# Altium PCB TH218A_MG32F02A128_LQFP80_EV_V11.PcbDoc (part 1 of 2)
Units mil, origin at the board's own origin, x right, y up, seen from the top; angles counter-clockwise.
Board outline 4370.08 x 2637.8 mil, 2 copper layers (Top Layer, Bottom Layer); 115 components, 136 nets, 568 pads, 236 vias.
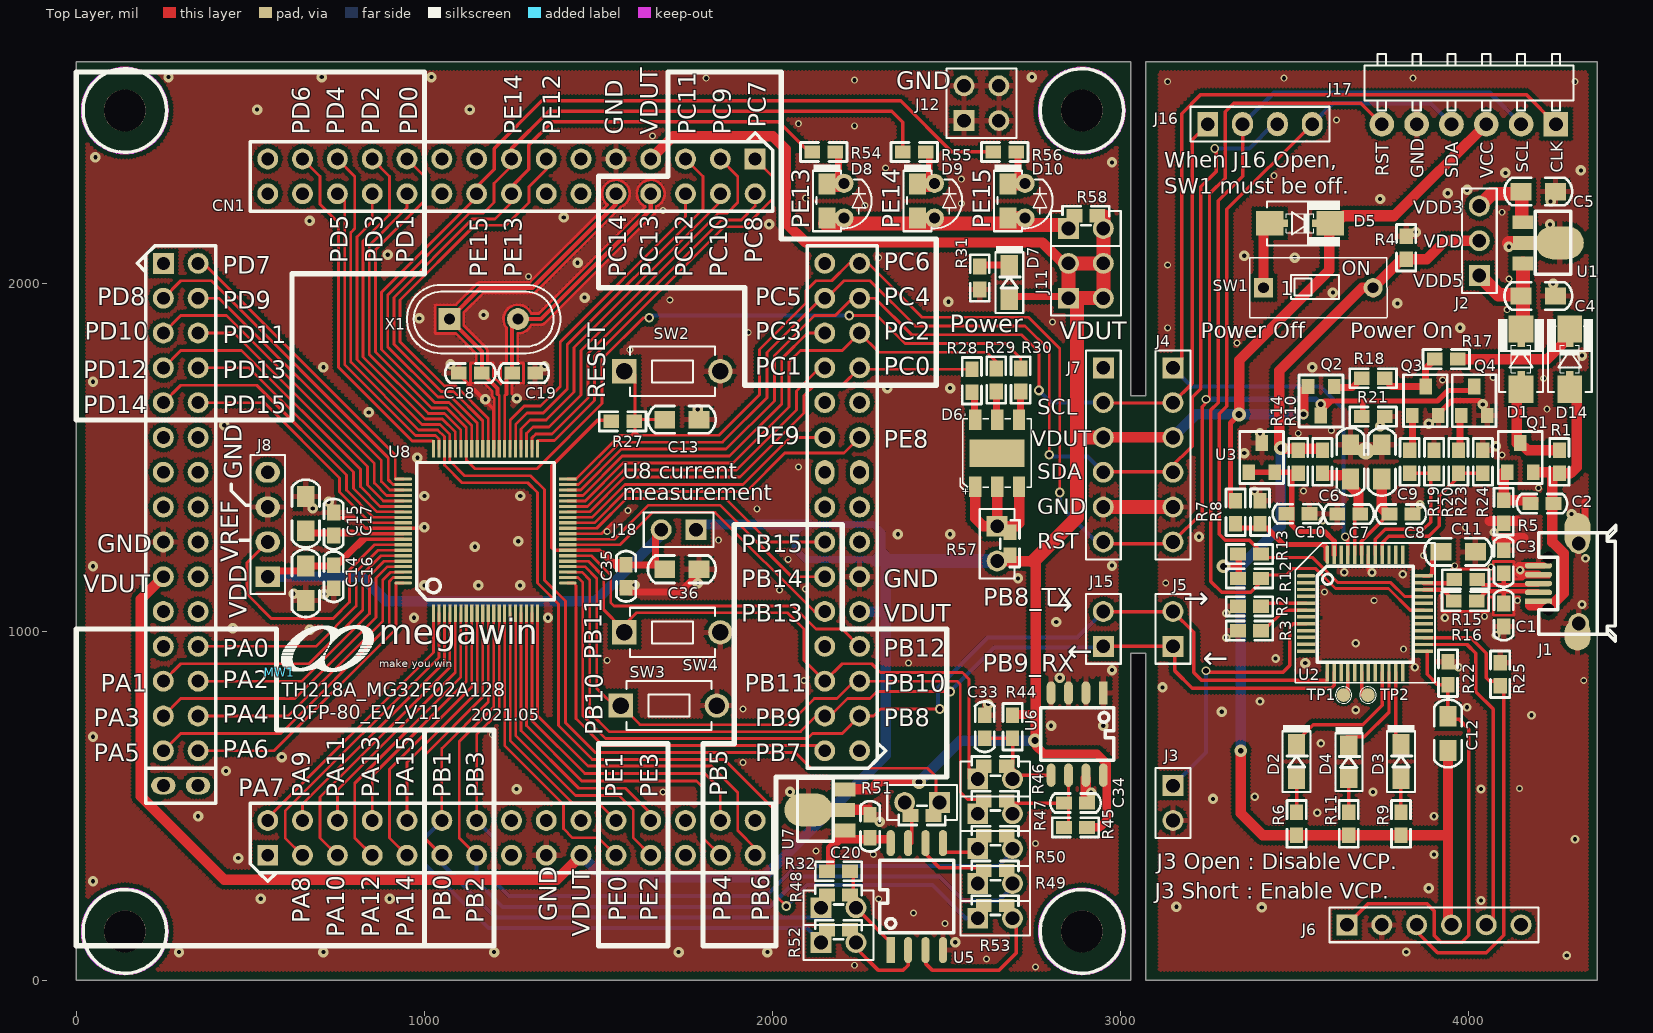
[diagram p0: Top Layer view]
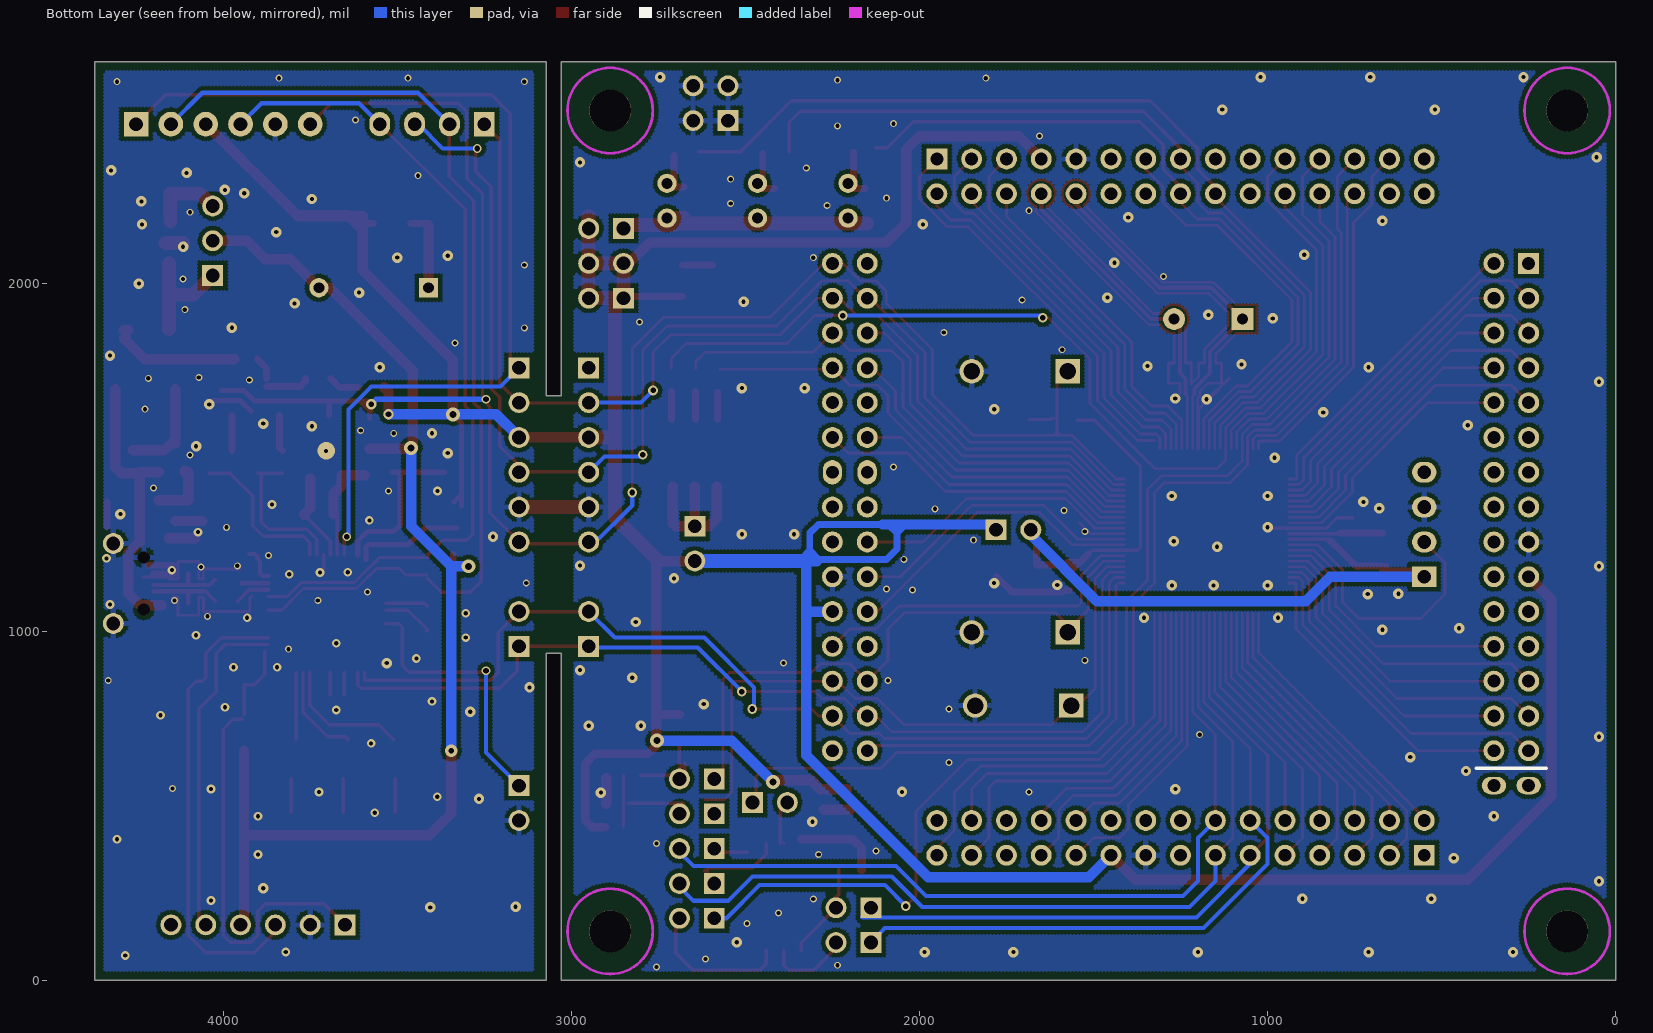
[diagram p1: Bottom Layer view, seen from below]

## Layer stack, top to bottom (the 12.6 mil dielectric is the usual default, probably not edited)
Top Layer: signal copper 1.4
Dielectric: dielectric 12.6, FR-4, Dk 4.8
Bottom Layer: signal copper 1.4

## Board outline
0,0 0,2637.8 3028.98,2637.8 3028.98,1678.74 3072.28,1678.74 3072.28,2637.8 4370.08,2637.8 4370.08,0 3072.28,0 3072.28,938.74 3028.98,938.74 3028.98,0

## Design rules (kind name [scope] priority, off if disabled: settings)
Clearance 12 [All] p1 off: gap=12
Clearance 7 [All] p2 off: gap=7
Clearance 6 [All] p3: gap=6
HoleSize 500-HoleSize [All] p1: absolutevalues=TRUE maxlimit=1500 minlimit=1 maxpercent=80.000 minpercent=20.000
PolygonConnect VIA [ISVIA] p1: connectstyle=Direct reliefconductorwidth=10 reliefentries=4 polygonreliefangle="90 Angle"
PolygonConnect "15 PolygonConnect" [All] p2: connectstyle=Relief reliefconductorwidth=15 reliefentries=4 polygonreliefangle="90 Angle"
RoomDefinition 2_MG32F02A128_V11 [InComponentClass('2_MG32F02A128_V11')] p1: confinementstyle=ConfineIn formatcopy=TRUE lockcomponents=FALSE outline -55,-85 4500,-85 4500,2740 -55,2740
RoomDefinition 1_MLink_V11 [InComponentClass('1_MLink_V11')] p2 off: confinementstyle=ConfineIn formatcopy=TRUE lockcomponents=FALSE outline -20,-126.26 4460,-126.26 4460,2920 -20,2920
RoutingVias [All] p1: holewidth=16 width=28 viastyle="Through Hole" minholewidth=16 minwidth=25 maxholewidth=28 maxwidth=50
ShortCircuit [All] p1 off: allowed=FALSE
SilkscreenOverComponentPads [All] p1: minsilkscreentomaskgap=10
SolderMaskExpansion [All] p1: expansion=4
UnRoutedNet [All] p1 off:
Width [All] p1: maxlimit=100 minlimit=6 preferedwidth=10
24 further rules are at their usual default settings.

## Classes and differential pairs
component class 1_MLink_V11: C1 C2 C3 C4 C5 C6 C7 C8 C9 C10 C11 C12 D1 D2 D3 D4 D5 D14 J1 J2 J3 J4 J5 J6 J16 J17 MW1 Q1 Q2 Q3 Q4 R1 R2 R3 R4 R5 R6 R7 R8 R9 R10 R11 R12 R13 R14 R15 R16 R17 R18 R19 R20 R21 R22 R23 R24 R25 SW1 TP1 TP2 U1 U2 U3
component class 2_MG32F02A128_V11: C13 C14 C15 C16 C17 C18 C19 C20 C33 C34 C35 C36 CN1 D6 D7 D8 D9 D10 J7 J8 J11 J12 J15 J18 R27 R28 R29 R30 R31 R32 R44 R45 R46 R47 R48 R49 R50 R51 R52 R53 R54 R55 R56 R57 R58 SW2 SW3 SW4 U5 U6 U7 U8 X1

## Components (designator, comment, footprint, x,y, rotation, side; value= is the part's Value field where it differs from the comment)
C1 "15pF" 0603C 4100.63,1048.74 r90 top
C2 "0.1uF" 0603C 4210.63,1368.74 r0 top
C3 "15pF" 0603C 4100.63,1201.74 r270 top
C4 "4.7uF" 0805C 4200,1965 r0 top
C5 "4.7uF" 0805C 4200,2265 r0 top
C6 "4.7uF" 0805C 3660.59,1488.74 r90 top
C7 "0.1uF" 0603C 3655.63,1338.74 r180 top
C8 "0.1uF" 0603C 3805.63,1338.74 r0 top
C9 "4.7uF" 0805C 3750.59,1488.74 r90 top
C10 "0.1uF" 0603C 3509.68,1339.69 r180 top
C11 "4.7uF" 0805C 3970,1230 r0 top
C12 "4.7uF" 0805C 3940.63,708.74 r90 top
C13 "4.7uF" 0805C 1740,1610 r180 top
C14 "4.7uF" 0805C 660,1140 r270 top
C15 "4.7uF" 0805C 660,1340 r90 top
C16 "0.1uF" 0603C 740,1158.74 r90 top
C17 "0.1uF" 0603C 740,1310 r270 top
C18 "NC" 0603C 1132.63,1743.74 r0 top
C19 "NC" 0603C 1285.63,1743.74 r180 top
C20 "1uF" 0603C 2280.63,441.74 r270 top
C33 "47pF" 0603C 2610,727.8 r270 top
C34 "47pF" 0603C 2870.63,508.74 r180 top
C35 "0.1uF" 0603C 1580,1160 r90 top
C36 "4.7uF" 0805C 1740,1180 r0 top
CN1 "QFP122-CKT" QFP122-P2.54-CKT 1250.63,1358.74 r0 top locked
D1 "1N5817" DIODE_SMA_SOD323 4150.59,1783.74 r90 top
D2 "Yellow" 0805D#1 3505.63,627.95 r90 top
D3 "Green" 0805D#1 3805.63,627.95 r90 top
D4 "Red" 0805D#2 3655.63,626.74 r90 top
D5 "1N5817" DIODE_SMA_SOD323 3515.59,2173.74 r0 top
D6 "GTG5050RGBC" LED6P_RGB_SMD_50X50 2645.63,1513.74 r90 top
D7 "Yellow" 0805D#1 2680.63,2003.74 r90 top
D8 "Red" LED38+0805 2205.63,2238.74 r90 top
D9 "Yellow" LED38+0805 2465.63,2238.74 r90 top
D10 "Green" LED38+0805 2725.63,2238.74 r90 top
D14 "1N5817" DIODE_SMA_SOD323 4290.59,1783.74 r90 top
J1 "Micro USB" JACK_USB_SMD290X220P065 4200.63,1139.21 r180 top locked (schematic designator J8)
J2 "2&3 (0 ohm)" PS3P254 4030.63,2023.74 r90 top
J3 "VCP Option" PS2P254 3150.63,558.74 r270 top
J4 "OnBoard ICP/SWD Connector" PS6P254 3150.63,1758.74 r270 top locked
J5 "NC" PS2P254 3150.63,958.74 r90 top
J6 "CON6" PS6P254 3650.63,158.74 r0 top
J7 "CON6" PS6P254 2950.63,1758.74 r270 top locked
J8 "1&2 (0 ohm)" PS4P254 550.63,1158.74 r90 top
J11 "CONN SOCKET 2x2/SM" PS2X2P254 2850.63,1958.74 r0 top
J12 "CONN SOCKET 2x2/SM" PS2X2P254 2550.63,2468.74 r0 top
J15 "NC" PS2P254 2950.63,958.74 r90 top
J16 "When J16 Open, SW1 must be off." PS4P254 3250.63,2458.74 r0 top
J17 "Off Board ICP/SWD Connector" PS6P254_90 4250.63,2458.74 r180 top locked
J18 "JUMPER" PS2P254 1780.63,1293.74 r180 top
MW1 "MW-A4" MEGAWIN_3.4 583.63,883.73 r0 top
Q1 "IRLML6402" SOT23 4148.13,1500.71 r0 top
Q2 "2N3906" SOT23 3576.09,1663.74 r180 top
Q3 "3904" SOT23_132 3875.63,1663.74 r0 top
Q4 "3904" SOT23_132 4015.63,1663.74 r0 top
R1 "NC" 0603R 4260.63,1488.74 r270 top
R2 "0" 0603R 3370.63,1073.74 r0 top
R3 "NC" 0603R 3370.63,1003.74 r0 top
R4 "3.3K" 0603R 3820.63,2103.74 r270 top
R5 "1M" 0603R 4100.63,1345.74 r270 top
R6 "1K" 0603R 3505.63,448.74 r270 top
R7 "30K" 0603R 3330.63,1343.74 r90 top
R8 "10K" 0603R 3400.63,1343.74 r270 top
R9 "1K" 0603R 3805.63,448.74 r270 top
R10 "10" 0603R 3580,1488.74 r90 top
R11 "1K" 0603R 3655.63,448.74 r270 top
R12 "1.5K" 0603R 3370.63,1153.74 r180 top
R13 "1.5K" 0603R 3370.63,1223.74 r180 top
R14 "1K" 0603R 3510.59,1488.74 r270 top
R15 "30" 0603R 3991.47,1151.05 r180 top
R16 "30" 0603R 3990.63,1088.74 r180 top
R17 "4.7K" 0603R 3935.59,1783.74 r0 top
R18 "1K" 0603R 3725.63,1728.74 r0 top
R19 "4.7K" 0603R 3830.63,1488.74 r270 top
R20 "10K" 0603R 3900.63,1488.74 r270 top
R21 "1M" 0603R 3725.63,1618.74 r180 top
R22 "47K" 0603R 3940.63,881.74 r90 top
R23 "4.7K" 0603R 3970.63,1488.74 r270 top
R24 "10K" 0603R 4040.63,1488.74 r270 top
R25 "47K" 0603R 4090.63,878.74 r270 top
R27 "47K" 0603R 1570,1605 r180 top
R28 "510" 0603R 2573.19,1721.74 r90 top
R29 "510" 0603R 2643.19,1723.74 r90 top
R30 "3K" 0603R 2713.19,1723.74 r90 top
R31 "1K" 0603R 2595.63,2016.74 r270 top
R32 "47K" 0603R 2190,312.8 r0 top
R44 "10K" 0603R 2690,727.8 r90 top
R45 "10K" 0603R 2870.63,438.74 r0 top
R46 "NC" PS2p254+0603 2590,577.8 r0 top
R47 "NC" PS2p254+0603 2590,477.8 r0 top
R48 "NC" PS2p254+0603 2140,207.8 r0 top
R49 "NC" PS2p254+0603 2590,277.8 r0 top
R50 "NC" PS2p254+0603 2590,377.8 r0 top
R51 "NC" PS2p254+0603 2480,510 r180 top
R52 "NC" PS2p254+0603 2140,107.8 r0 top
R53 "NC" PS2p254+0603 2590,177.8 r0 top
R54 "510" 0603R 2147.63,2378.74 r180 top
R55 "510" 0603R 2407.63,2378.74 r180 top
R56 "510" 0603R 2667.63,2378.74 r180 top
R57 "0" PS2p254+0603 2645.63,1303.74 r270 top
R58 "0" PS2p254+0603 2850.63,2158.74 r0 top
SW1 "SW KEY-SPST" DIP2_SW 3410.67,1988.74 r0 top
SW2 "SW TACT-SPST" SW_T_2P 1712.83,1748.74 r0 top
SW3 "SW TACT-SPST" SW_T_2P 1702.83,788.74 r0 top
SW4 "SW TACT-SPST" SW_T_2P 1712.83,998.74 r0 top
TP1 "T POINT A" PIN1_1H0 3640.63,818.74 r270 top
TP2 "T POINT A" PIN1_1H0 3710.63,818.74 r270 top
U1 "AIC1734-33(SOT-89)" SOT89 4155.63,2117.8 r270 top
U2 "MG84FG516_LQFP48" LQFP48_7X7_050 3702.1,1053.13 r270 top locked
U3 "TL431A" SOT23 3405.59,1500.71 r0 top
U5 "MX25LXX-SOP" SO8_208P127 2415,240 r0 top
U6 "24C16-SOP" SO8_150P127 2950.63,824.96 r270 top
U7 "AIC1734-33(SOT-89)" SOT89 2210,489.06 r90 top
U8 "MG32F02A128_LQFP80" QFP80-P0.4-Z12X12 1176.02,1289.96 r0 top
X1 "NC" X49U 1170.63,1898.74 r0 top

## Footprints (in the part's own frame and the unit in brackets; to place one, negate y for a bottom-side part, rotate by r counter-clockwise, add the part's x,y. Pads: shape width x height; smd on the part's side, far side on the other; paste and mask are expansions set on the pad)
0603C [mil]
  rect 45x38 smd: 1(33,0) 2(-33,0)
  silkscreen extent -72,-28 72,28
0603R [mil]
  rect 45x38 smd: 1(33,0) 2(-33,0)
  silkscreen extent -67,-28 67,28
0805C [mil]
  rect 60x50 smd: 1(-49.21,0) 2(49.21,0)
  silkscreen extent -97,-39 97,39
0805D#1 [mil]
  rect 60x50 smd: 1(-49.21,0) 2(49.21,0)
  silkscreen extent -87,-40 105,40
0805D#2 [mil]
  rect 55.12x51.18 smd: 1(-48,0) 2(48,0)
  silkscreen extent -84,-39 100,38
DIODE_SMA_SOD323 [mm]
  rect 2x1.8 smd: 1(-2.2,0) 2(2.2,0)
  rect 0.95x0.54 smd: 1(-1.35,0) 2(1.35,0)
  silkscreen extent -2.4,-1.68 2.92,1.68
DIP2_SW [mm]
  rect 1.4x1.4 hole 0.8: 1(0,0)
  round 1.4 hole 0.8: 2(8,0)
  silkscreen extent -1.02,-2.2 9.02,2.2
JACK_USB_SMD290X220P065 [mm]
  rect 1.9x1.8 on Mech2: 0(-2.85,-1.15) 0(-2.85,1.15)
  round 0.8 hole 0.9 unplated: 1(-0.7,1.9) 5(-0.7,-1.9)
  rect 2x0.4 smd: 1(0,1.3)
  oval 2x0.4 smd: 2(0,0.65) 3(0,0) 4(0,-0.65) 5(0,-1.3)
  round 1.524 hole 1: 5(-2.931,2.921) 6(-2.931,-2.921)
  oval 1.9x2.3 smd: 5(-2.85,3.75)
  oval 1.9x2.794 smd: 6(-2.85,-3.75)
  silkscreen extent -5.65,-4.25 -0.01,4.2
LED6P_RGB_SMD_50X50 [mm]
  rect 2x4 smd: 0(0,0)
  rect 1.5x0.9 smd: 1(-2.45,1.6) 2(2.45,1.6) 3(-2.45,0) 4(2.45,0) 5(-2.45,-1.6) 6(2.45,-1.6)
  silkscreen extent -2.63,-2.5 2.5,2.69
LED38+0805 [mm]
  round 1.4 hole 0.8: 1(-1.27,0) 2(1.27,0)
  rect 1.524x1.27 smd: 1(-1.267,1.237) 2(1.233,1.237)
  silkscreen extent -2.23,-2.02 2.64,2.25
LQFP48_7X7_050 [mm]
  oval 0.254x1.35 smd: 1(-2.75,-4.292)
  rect 0.254x1.35 smd: 2(-2.25,-4.292) 3(-1.75,-4.292) 4(-1.25,-4.292) 5(-0.75,-4.292) 6(-0.25,-4.292) 7(0.25,-4.292) 8(0.75,-4.292) 9(1.25,-4.292) 10(1.75,-4.292) 11(2.25,-4.292) 12(2.75,-4.292) 25(2.763,4.292) 26(2.263,4.292) 27(1.763,4.292) 28(1.263,4.292) 29(0.763,4.292) 30(0.263,4.292) 31(-0.237,4.292) 32(-0.737,4.292) 33(-1.237,4.292) 34(-1.737,4.292) 35(-2.237,4.292) 36(-2.737,4.292)
  rect 1.35x0.254 smd: 13(4.286,-2.744) 14(4.286,-2.244) 15(4.286,-1.744) 16(4.286,-1.244) 17(4.286,-0.744) 18(4.286,-0.244) 19(4.286,0.256) 20(4.286,0.756) 21(4.286,1.256) 22(4.286,1.756) 23(4.286,2.256) 24(4.286,2.756) 37(-4.286,2.756) 38(-4.286,2.256) 39(-4.286,1.756) 40(-4.286,1.256) 41(-4.286,0.756) 42(-4.286,0.256) 43(-4.286,-0.244) 44(-4.286,-0.744) 45(-4.286,-1.244) 46(-4.286,-1.744) 47(-4.286,-2.244)
  oval 1.35x0.254 smd: 48(-4.286,-2.744)
  silkscreen extent -5.15,-5.09 5.05,5.11
MEGAWIN_3.4 [mil]
  silkscreen extent 5,3 272,136
PIN1_1H0 [mm]
  round 1 smd: 1(0,0)
  silkscreen extent -0.6,-0.6 0.6,0.6
PS2P254 [mil]
  rect 60x60 hole 39.37: 1(0,0)
  round 60 hole 39.37: 2(100,0)
  silkscreen extent -50,-50 150,50
PS2p254+0603 [mil]
  rect 60x60 hole 39.37: 1(0,0)
  rect 45x38 smd: 1(17,36.85) 2(83,36.85)
  round 60 hole 39.37: 2(100,0)
  silkscreen extent -50,-50 150,64
PS2X2P254 [mil]
  rect 60x60 hole 39.37: 1(0,0)
  round 60 hole 39.37: 2(0,100) 3(100,0) 4(100,100)
  silkscreen extent -50,-50 150,150
PS3P254 [mil]
  rect 60x60 hole 39.37: 1(0,0)
  round 60 hole 39.37: 2(100,0) 3(200,0)
  silkscreen extent -50,-50 250,50
PS4P254 [mil]
  rect 60x70 hole 39.37: 1(0,0)
  oval 60x70 hole 39.37: 2(100,0) 3(200,0) 4(300,0)
  silkscreen extent -50,-50 350,50
PS6P254 [mil]
  rect 60x60 hole 39.37: 1(0,0)
  round 60 hole 39.37: 2(100,0) 3(200,0) 4(300,0) 5(400,0) 6(500,0)
  silkscreen extent -50,-50 550,50
PS6P254_90 [mm]
  rect 1.8x1.8 hole 1: 1(0,0)
  round 1.8 hole 1: 2(2.54,0) 3(5.08,0) 4(7.62,0) 5(10.16,0) 6(12.7,0)
  silkscreen extent -1.27,-5.11 13.97,-1
QFP80-P0.4-Z12X12 [mm]
  rect 0.229x1.27 smd: 1(-3.8,-6) 2(-3.4,-6) 3(-3,-6) 4(-2.6,-6) 5(-2.2,-6) 6(-1.8,-6) 7(-1.4,-6) 8(-1,-6) 9(-0.6,-6) 10(-0.2,-6) 11(0.2,-6) 12(0.6,-6) 13(1,-6) 14(1.4,-6) 15(1.8,-6) 16(2.2,-6) 17(2.6,-6) 18(3,-6) 19(3.4,-6) 20(3.8,-6) 41(3.8,6) 42(3.4,6) 43(3,6) 44(2.6,6) 45(2.2,6) 46(1.8,6) 47(1.4,6) 48(1,6) 49(0.6,6) 50(0.2,6) 51(-0.2,6) 52(-0.6,6) 53(-1,6) 54(-1.4,6) 55(-1.8,6) 56(-2.2,6) 57(-2.6,6) 58(-3,6) 59(-3.4,6) 60(-3.8,6)
  oval 1.27x0.229 smd: 21(6,-3.8) 61(-6,3.8) 80(-6,-3.8)
  rect 1.27x0.229 smd: 22(6,-3.4) 23(6,-3) 24(6,-2.6) 25(6,-2.2) 26(6,-1.8) 27(6,-1.4) 28(6,-1) 29(6,-0.6) 30(6,-0.2) 31(6,0.2) 32(6,0.6) 33(6,1) 34(6,1.4) 35(6,1.8) 36(6,2.2) 37(6,2.6) 38(6,3) 39(6,3.4) 40(6,3.8) 62(-6,3.4) 63(-6,3) 64(-6,2.6) 65(-6,2.2) 66(-6,1.8) 67(-6,1.4) 68(-6,1) 69(-6,0.6) 70(-6,0.2) 71(-6,-0.2) 72(-6,-0.6) 73(-6,-1) 74(-6,-1.4) 75(-6,-1.8) 76(-6,-2.2) 77(-6,-2.6) 78(-6,-3) 79(-6,-3.4)
  silkscreen extent -5,-5 5,5
QFP122-P2.54-CKT [mil]
  rect 60x60 hole 37: 1(-700,-1000) 61(700,1000) 91(-1000,700)
  round 60 hole 37: 2(-700,-900) 3(-600,-1000) 4(-600,-900) 5(-500,-1000) 6(-500,-900) 7(-400,-1000) 8(-400,-900) 9(-300,-1000) 10(-300,-900) 11(-200,-1000) 12(-200,-900) 13(-100,-1000) 14(-100,-900) 15(0,-1000) 16(0,-900) 17(100,-1000) 18(100,-900) 19(200,-1000) 20(200,-900) 21(300,-1000) 22(300,-900) 23(400,-1000) 24(400,-900) 25(500,-1000) 26(500,-900) 27(600,-1000) 28(600,-900) 29(700,-1000) 30(700,-900) 31(1000,-700) 32(900,-700) 33(1000,-600) 34(900,-600) 35(1000,-500) 36(900,-500) 37(1000,-400) 38(900,-400) 39(1000,-300) 40(900,-300) 41(1000,-200) 42(900,-200) 43(1000,-100) 44(900,-100) 45(1000,0) 46(900,0) 49(1000,200) 50(900,200) 51(1000,300) 52(900,300) 53(1000,400) 54(900,400) 55(1000,500) 56(900,500) 57(1000,600) 58(900,600) 59(1000,700) 60(900,700) 62(700,900) 63(600,1000) 64(600,900) 65(500,1000) 66(500,900) 67(400,1000) 68(400,900) 69(300,1000) 70(300,900) 71(200,1000) 72(200,900) 73(100,1000) 74(100,900) 75(0,1000) 76(0,900) 77(-100,1000) 78(-100,900) 79(-200,1000) 80(-200,900) 81(-300,1000) 82(-300,900) 83(-400,1000) 84(-400,900) 85(-500,1000) 86(-500,900) 87(-600,1000) 88(-600,900) 89(-700,1000) 90(-700,900) 92(-900,700) 93(-1000,600) 94(-900,600) 95(-1000,500) 96(-900,500) 97(-1000,400) 98(-900,400) 99(-1000,300) 100(-900,300) 101(-1000,200) 102(-900,200) 103(-1000,100) 104(-900,100) 105(-1000,0) 106(-900,0) 107(-1000,-100) 108(-900,-100) 109(-1000,-200) 110(-900,-200) 111(-1000,-300) 112(-900,-300) 113(-1000,-400) 114(-900,-400) 115(-1000,-500) 116(-900,-500) 117(-1000,-600) 118(-900,-600) 119(-1000,-700) 120(-900,-700)
  oval 55x70 hole 37: 47(1000,100) 48(900,100)
  oval 70x50 hole 37: 121(-1000,-800) 122(-900,-800)
  silkscreen extent -1075,-1075 1075,1075
SO8_150P127 [mil]
  rect 67x25 smd: 1(0,0)
  oval 67x25 smd: 2(0,-50) 3(0,-100) 4(0,-150) 5(236.22,-150) 6(236.22,-100) 7(236.22,-50) 8(236.22,0)
  silkscreen extent 43,-180 193,30
SO8_208P127 [mm]
  rect 0.6x1.9 smd: 1(-1.905,-3.9)
  oval 0.6x1.9 smd: 2(-0.635,-3.9) 3(0.635,-3.9) 4(1.905,-3.9) 5(1.905,3.9) 6(0.635,3.9) 7(-0.635,3.9) 8(-1.905,3.9)
  silkscreen extent -2.69,-2.63 2.69,2.63
SOT23 [mil]
  rect 36x43.31 smd: 1(-37.5,-41.97) 2(37.5,-41.97)
  rect 36x46.06 smd: 3(0.5,41.97)
  silkscreen extent -63,-74 63,75
SOT23_132 [mil]
  rect 36x43.31 smd: 1(-37.5,-41.97) 3(37.5,-41.97)
  rect 36x46.06 smd: 2(0.5,41.97)
  silkscreen extent -63,-74 63,75
SOT89 [mm]
  rect 1.016x1.5 smd: 1(-1.5,0) 3(1.5,0)
  oval 2.4x3.5 smd: 2(0,2.7)
  rect 1.016x2.6 smd: 2(0,0.6)
  silkscreen extent -2.3,0.9 2.3,3.5
SW_T_2P [mil]
  rect 70x70 hole 47.24: 1(-137.79,0)
  round 70 hole 47.24: 2(137.8,0)
  silkscreen extent -122,-71 122,71
X49U [mm]
  rect 1.6x1.6 hole 0.8: 1(-2.5,0)
  round 1.6 hole 0.8: 2(2.5,0)
  silkscreen extent -5.6,-2.5 5.6,2.5

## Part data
C1 C3 C7 C12 C13 C14 C15 C16 C17 C35 C36: library part "CAP NP_Dup1"
C2 C8 C10: library part "CAP NP"
C4 C5: library part "C NP"
C6 C9 C11: library part CAP
C18 C19: library part "C NP_Dup1"
C20 C33 C34: library part CAP-NP
D1 D5 D14: library part "DIODE SCHOTTKY"
D2 D3 D4: library part Led0_0
D6: library part LED_GTG5050RGBC
D7 D8 D9 D10: library part LED
J1 J7: library part CON6_Dup1
J2: library part CON3
J3 J5 J15: library part CON2
J4 J17: library part CON6
J8 J16: library part CON4
MW1: library part MW_A4_2
Q1: library part "MOSFET P GSD"
Q2: library part 2N3906_0
Q3 Q4: library part "NPN BCE"
R1 R2 R3 R4 R27: library part R_Dup4
R5 R6 R7 R8 R9 R11 R12 R13 R17 R18 R19 R22 R23 R25: library part R_Dup2
R10 R14 R15 R16 R28 R29 R30 R31 R32 R46 R47 R48 R49 R50 R51 R52 R53 R54 R55 R56 R57 R58: library part R_Dup5
R20 R21 R24: library part R_Dup1
R44 R45: library part R
U1 U7: library part AIC1722-33
U3: library part TL431/CYL
U5: library part ICM-25LXX
U6: library part ICM-24CXX
U8: library part IC-MG32F02A128-LQFP80
X1: library part CRYSTAL

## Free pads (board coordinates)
  round 120 hole 120 unplated: 0(140,140) 0(140,2497.8) 0(2888.98,140) 0(2888.98,2497.8)

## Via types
v1: diameter 30, hole 12, Top Layer to Bottom Layer, tented both sides, 108 vias
v2: diameter 20, hole 12, Top Layer to Bottom Layer, tented both sides, 74 vias
v3: diameter 25, hole 12, Top Layer to Bottom Layer, tented both sides, 33 vias
v4: diameter 28, hole 16, Top Layer to Bottom Layer, tented both sides, 8 vias
v5: diameter 40, hole 20, Top Layer to Bottom Layer, tented both sides, 5 vias
v6: diameter 25, hole 16, Top Layer to Bottom Layer, tented both sides, 4 vias
v7: diameter 30, hole 16, Top Layer to Bottom Layer, tented both sides, 2 vias
v8: diameter 50, hole 12, Top Layer to Bottom Layer, tented both sides, 1 vias
v9: diameter 35, hole 16, Top Layer to Bottom Layer, tented both sides, 1 vias

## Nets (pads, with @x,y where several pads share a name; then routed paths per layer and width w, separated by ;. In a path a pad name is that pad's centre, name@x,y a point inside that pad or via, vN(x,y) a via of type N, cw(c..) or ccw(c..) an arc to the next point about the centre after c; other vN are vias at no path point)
2.495V: C10.1 R14.1 U2.47 U3.1 U3.2 | length 479.3
  Top Layer w15: U3.1@3365.59,1458.74 U3.1@3368.09,1458.74 U3.2@3443.09,1458.74 3510.59,1458.74 R14.1@3515.59,1458.74 ; R14.1@3491.85,1456.77 3491.85,1455.74 3491.85,1339.69 3491.85,1307.52 3510.63,1288.74 3585.63,1288.74 3613.77,1260.6 U2.47@3613.77,1221.87
CHIP_VDD: C14.1 C16.1 C35.1 C36.1 J8.1 J18.2 R27.1 U8.27 U8.72 | length 2651.2
  Top Layer w8: 803.03,1253.74 815.63,1266.34
  Top Layer w9: 810.63,1243.74 833.23,1266.34 ; 815.63,1266.34 833.23,1266.34 ; U8.72@939.8,1266.34 833.23,1266.34
  Top Layer w10: 1515.63,1223.74 1504.53,1234.84 U8.27@1412.24,1234.84 1374.53,1234.84 1365.63,1243.74 1365.63,1475.92 1498.45,1608.74 1537,1608.74 R27.1@1547.63,1608.74
  Top Layer w20: J8.1@575,1175 660,1175 C14.1@670,1175 ; C14.1@660.63,1188 C14.1@670,1188 ; C14.1@670,1190 740,1190 C16.1@746.89,1190 ; C16.1@740,1188 744.89,1188 C16.1@746.89,1190 ; 815.63,1258.74 C16.1@746.89,1190 ; 1515.63,1223.74 1557.63,1181.74 C35.1@1575.63,1181.74 ; 1540,1200 C35.1@1575.63,1200 ; C35.1@1575.63,1191.74 1580,1191.74 1665,1191.74 1665,1278.11 J18.2@1680.63,1293.74
  Bottom Layer w30: J8.1@550.63,1158.74 820.63,1158.74 890.63,1088.74 1490.63,1088.74 1680.63,1278.74 J18.2@1680.63,1293.74
D+: C3.1 J1.3 R15.2 | length 211.2
  Top Layer w12: R15.2@4024.47,1151.05 4040.3,1135.21 J1.3@4200.63,1135.21 ; 4100.63,1140.21 C3.1@4100.63,1168.74
D-: C1.1 J1.2 R16.2 | length 219.3
  Top Layer w12: R16.2@4023.63,1088.74 4052.1,1117.21 J1.2@4200.63,1117.21 ; C1.1@4100.63,1081.74 4100.63,1112.21
DET_VDUT: R7.2 R8.1 U2.48 | length 317.8
  Top Layer w15: R7.2@3330.63,1298.74 3400.63,1298.74 3420.63,1298.74 3467.86,1251.51 3582.86,1251.51 3590.63,1243.74 3590.63,1221.87 U2.48@3590.63,1208.74
DUT_CLK: J4.1 J17.1 U2.45 | length 2848.1
  Top Layer w10: J4.1@3150.63,1758.74 3175.63,1783.74 3175.63,2488.74 3230.63,2543.74 4165.63,2543.74 J17.1@4250.63,2458.74 ; v6@3640.51,1273.74 3643.01,1271.24 3653.14,1261.11 ; U2.45@3653.14,1221.87 3653.14,1261.11 ; v6@3653.14,1273.74 3653.14,1261.11
  Bottom Layer w12: J4.1@3150.63,1758.74 3204.37,1705 3575,1705 3640.51,1639.49 v6@3640.51,1273.74
  other v6: 3645.51,1273.74
FAIL: D4.2 U2.22 | length 278.6
  Top Layer w10: D4.2@3640.63,689.74 3649.63,698.74 3655.63,698.74 3700.63,698.74 3771.25,769.36 U2.22@3771.25,884.39
FLASH_CEN: R32.1 R48.2 U5.1 | length 275.7
  Top Layer w10: R32.1@2233,317.8 2233,312.8 2233,244.8 2255,222.8 2255,207.8 2255,192.8 2340,107.8 U5.1@2340,86.46
FLASH_D0: R50.1 U5.5 | length 94.3
  Top Layer w10: U5.5@2495,367.8 R50.1@2589.25,367.8
FLASH_D1: R52.2 U5.2 | length 261.8
  Top Layer w10: R52.2@2240,127.8 R52.2@2240,107.8 2240,92.8 2305,27.8 2375,27.8 2390,42.8 U5.2@2390,86.46
FLASH_D2: R53.2 U5.3 | length 427.7
  Top Layer w10: U5.3@2440,86.46 2440,47.8 2460,27.8 2650,27.8 2700,77.8 R53.2@2700,177.8
FLASH_D3: R51.2 U5.7 | length 133
  Top Layer w10: R51.2@2385,520 2387.5,517.5 2400,505 2400,473.15 U5.7@2400,393.54 ; U5.7@2390,393.19 U5.7@2390,393.54
FLASH_SCK: R49.1 U5.6 | length 241.4
  Top Layer w10: U5.6@2440,393.54 2440,362.8 2480,322.8 2607,322.8 2608.85,322.8 2610.15,321.5 2610.15,314.65 2610.15,307.8 2612,309.65 R49.1@2617,314.65
GND_POWER: C1.2 C3.2 C4.2 C5.2 C6.2 C7.1 C8.1 C9.2 C10.2 C11.2 C13.1 C14.2 C15.2 C16.2 C17.2 C18.2 C19.2 C20.2 C33.2 C34.2 C35.2 C36.2 CN1.17 CN1.41 CN1.69 CN1.107 J1.4 J1.5 J1.6 J3.2 J4.5 J6.2 J7.5 J8.3 J12.1 J12.2 J12.3 J12.4 J17.5 Q3.3 Q4.3 R2.2 R3.2 R4.2 R5.1 R8.2 R20.2 R21.2 R22.1 R24.2 R25.2 R31.1 SW2.2 SW3.2 SW4.2 U1.2 U2.42 U3.3 U5.4 U6.1 U6.2 U6.3 U6.4 U6.7 U7.2 U8.30 U8.49 U8.70 | length 6667.9
  Top Layer w8: U8.49@1200.89,1526.18 1200.89,1561.18 ; 1201.39,1561.18 1201.39,1670.51 cw(c1210.39,1683.74) 1194.39,1683.74 1194.39,1692.35 1172,1714.74 1133.13,1714.74 1133.13,1772.74 1149.63,1772.74 1149.63,1798.69 1091.07,1857.24 1030.71,1857.24 1030.71,1940.24 1091.07,1940.24 1150.88,2000.04 ; 1220.14,1711.86 1198.13,1733.87 1198.13,1772.74 1181.63,1772.74 1181.63,1805.32 ; 1220.13,1714.74 1220.13,1772.74 1236.63,1772.74 1236.63,1872.85 cw(c1269.05,1898.74) 1307.34,1914.74 1329,1914.74 1634.63,2220.37 ; 1252.14,1683.74 1252.14,1714.74 1285.13,1714.74 1285.13,1772.74 1268.63,1772.74 1268.63,1857.25 ccw(c1269.05,1898.74) 1307.34,1882.74 1335.63,1882.74 ; 1321.94,1977.43 cw(c1310.63,1988.74) 1310.63,1972.74 ; 1346.94,1887.43 cw(c1335.63,1898.74) 1335.63,1882.74 ; U8.30@1412.24,1282.09 1508.98,1282.09 1520.63,1293.74 1540.63,1313.74 ; 1561.94,2217.43 ccw(c1550.63,2228.74) 1564.82,2221.34 ; 1634.63,2222.08 cw(c1650.63,2258.74) 1690.63,2258.74 cw(c1650.63,2258.74) 1666.63,2222.08 1666.63,2213.74 ; 1661.94,2202.43 ccw(c1650.63,2213.74) 1666.63,2213.74 ; 3917.8,1104.53 3924.13,1098.2 3924.13,1058.74 3990.13,1058.74 ; 3950.63,1181.05 3960,1181.05 3990.97,1181.05 ; 3991.13,1058.74 4045.53,1058.74 4057.13,1058.74 4057.13,1098.2 ; 3991.97,1181.05 4057.97,1181.05 4057.97,1152.21 4070.63,1152.21 4070.63,1187.05 4070.63,1202.24 4130.63,1202.24 4130.63,1152.21 4155.45,1152.21 cw(c4169.13,1139.21) 4169.13,1158.09 4200.63,1158.09 J1.4@4232.13,1158.09 ; 4059.14,1100.21 4070.63,1100.21 4070.63,1048.24 4130.63,1048.24 4130.63,1090.64 4130.63,1100.21 4140.63,1100.21 4146.27,1100.21 ; 1150.89,2000.05 cw(c1162.2,1988.74) 1162.2,2004.74 ; 1150.88,2000.04 cw(c1162.2,1988.74) 1162.2,2004.74 ; 1162.2,2004.74 1304,2004.74 1526.27,2227.01 cw(c1550.63,2258.74) 1590.63,2258.74 cw(c1550.63,2258.74) 1564.82,2221.34 ; 1176.93,1816.64 cw(c1165.63,1805.32) 1181.63,1805.32 ; 1176.94,1816.63 cw(c1165.63,1805.32) 1181.63,1805.32 ; 1176.93,1816.64 1113.7,1879.87 1113.7,1917.61 1168.83,1972.74 1310.63,1972.74 ; 1310.63,1972.74 ccw(c1310.63,1988.74) 1321.96,1977.44 1561.93,2217.41 ccw(c1550.63,2228.74) 1564.82,2221.34 ; 1335.63,1882.74 ccw(c1335.63,1898.74) 1346.96,1887.44 1661.93,2202.41 ccw(c1650.63,2213.74) 1666.63,2213.74
  Top Layer w9: 800.63,1328.74 831.54,1297.83 U8.70@939.8,1297.84
  Top Layer w10: C17.2@755.63,1328.74 800.63,1328.74 ; U8.70@939.8,1297.84 v1@995.63,1297.83 ; C18.2@1110.63,1728.74 1173.13,1666.24 1199.65,1639.72 U8.49@1199.65,1526.18 ; 3712.19,1177.75 U2.42@3712.19,1221.87
  Top Layer w15: Q3.3@3920.88,1634.03 3951.83,1664.98 4029.29,1664.98 v1(4040.53,1653.74)
  Top Layer w20: C35.2@1570,1118.9 C35.2@1575.63,1118.9 ; C35.2@1575.67,1118.9 C35.2@1580.05,1118.93 ; C35.2@1590,1115 1605.12,1115.09 ; 1605.12,1115 1736.38,1115 ; 1736.38,1115.87 1773.3,1153.22 C36.2@1780,1160 ; v3@4144.51,1166.05 4147.8,1166.05 J1.4@4200.63,1166.05 ; 4144.51,1191.64 4147.8,1191.64 4200.63,1191.64 J1.5@4215.63,1191.64 ; J1.6@4334.28,1302.62 4334.28,1373.74
  Top Layer w30: U7.2@2200,490 C20.2@2275,490 ; C34.2@2900.63,506.84 2900.63,508.74 2900.63,538.74 U6.7@2900.63,580.64 ; 4060.63,1318.74 4100.63,1318.74 4137.63,1318.74 ; 4080.63,1268.74 4100.63,1268.74 4157.63,1268.74
  Top Layer w40: J7.5@2950.63,1358.74 J4.5@3150.63,1358.74 ; v1@4115.53,2117.8 U1.2@4165.59,2117.8
  other v1: 295.63,80.64 710.63,80.64 1200.63,80.64 1730.63,80.64 1985.63,80.64 2525.53,108.74 3405.53,208.74 3160.63,210.64 530.53,233.74 900.53,233.74 3885.53,263.74 48.63,283.84 465.63,350.64 2308.19,454.89 350.63,470.64 3265.63,520.64 2915.53,538.74 2050.63,540.64 1265.53,548.74 430.63,600.64 590.63,640.64 48.63,698.84 2800.63,730.64 2950.63,730.64 3290.63,770.64 2620,792.8 3120.63,840.64 2825.53,868.74 2975.63,890.64 3530.63,910.64 670.63,1006.5 450.63,1010.64 2815.53,1028.74 970.63,1040.64 1355.63,1040.64 713.07,1108.74 625,1110 1000.63,1133.74 1155.53,1133.74 1275.53,1133.74 1605,1135 1786.1,1140.58 2705.53,1153.74 48.63,1188.84 2975.63,1190.64 1145.53,1245 1270,1260.64 3225.53,1273.74 2360.63,1280.64 2510.63,1280.64 1000.63,1300.64 4295.53,1338.74 680,1355 725.53,1373.74 1000.63,1390.64 1275.63,1390.64 980.63,1500.64 3355.53,1513.74 4078.19,1533.74 3400.63,1570.64 3745.59,1591.18 425.53,1593.74 3885.53,1598.74 840.63,1630.64 1785.53,1640 1175.63,1668.74 1265.63,1670.64 2330.63,1700.64 2510.63,1700.64 48.63,1718.84 710.63,1760.64 3550.59,1760.64 1345.53,1763.74 1075.53,1768.74 4325.53,1793.74 3975.59,1873.74 985.63,1900.64 1170.63,1910.64 3795.53,1943.74 2505.53,1948.74 1460.63,1960.64 3610,1975 4242.63,2000.64 1440.63,2060.64 3500.63,2075.35 3355.63,2080.64 895.53,2083.74 4115.53,2106.74 3848.19,2148.74 1990.63,2170.64 4233.63,2170.64 670.63,2180.64 1400.63,2190.64 4235.53,2236.74 3745.53,2243.74 3940,2260 3995.53,2269.74 4105.53,2318.74 4322.63,2325.64 2975.53,2348.74 55.53,2363.74 520,2500.64 1130.63,2500.64 265.53,2593.74 705.53,2593.74 1020.53,2593.74 2745.53,2593.74
  other v2: 2755.53,37.8 2235.53,42.8 2615,60.64 2495.53,162.8 2405.53,192.8 2305.53,232.8 2290,360.64 2125,370.64 2755.53,392.8 1685.53,540 4145.63,550.64 1915.53,625 1195.53,705 1915.53,778.74 2090.63,860.64 4330.63,860.64 2390.63,910.64 1525.53,918.74 3812.63,950.64 4045.53,1045 3728.63,1090.64 4140.63,1090.64 3585.53,1114.74 2020.63,1120.64 2095.53,1123.74 3130,1140.64 4063.97,1187.05 3960,1190 2045.53,1208.74 3870,1220 1845.53,1263.74 1525.63,1288.74 3990.63,1300.64 1585.63,1348.74 1955.53,1353.74 3525.53,1405 4200.63,1413.74 2075.53,1473.74 4095.53,1508.74 3510.59,1570.64 3605.53,1578.71 4225,1640 3925.53,1723.74 4215.53,1728.74 4070.59,1730.64 1590.63,1810.64 3335,1830 1930.63,1860.64 3135.53,1873.74 2805,1890.64 4110.63,1925.64 1705.53,1953.74 4115.53,2013.74 1300,2020.64 3135.53,2053.74 2305.53,2075 4095.59,2205.64 1685.53,2210 2265.53,2225 2542.78,2230.64 2095.53,2246 2542.78,2300.64 3440.63,2310.64 2325.53,2333 1655.53,2425 2235.53,2454 2075.53,2460 3620.63,2470.64 3135.63,2580.64 4305.63,2580.64 2235.53,2585 1810,2590.64 3470,2590.64 3840,2590.64
  other v3: 4281.63,70.64 3820.63,80.64 4035.53,228.74 3900.63,360.64 4305.53,404.74 3900.63,470.64 3565,480.64 3385.53,526.74 3725,540.64 4035.53,548.74 3575.53,680 4180.63,760.64 3675.53,775.74 3995.53,783.74 3400.63,800.64 3845.53,898.74 3970.63,898.74 3445.53,923.74 3675.53,967.74 3303.7,983.74 4078.63,990.64 3931.63,1040.64 3303.7,1053.74 4325.53,1078.74 3810.63,1165.74 3722.63,1170.74 3642.63,1171.74 4147.8,1177.6 4335.53,1211.45 4073.07,1286.74 3580.63,1320.64 3860,1366.3 3385,1405
  other v8: 3705,1520
I2C_SCL: C34.1 R45.2 R47.2 U6.6 | length 307.5
  Top Layer w10: R47.2@2678.9,508.74 2690,508.74 C34.1@2837.63,508.74 ; R45.2@2850.63,440 2850.63,508.74 U6.6@2850.63,588.74
I2C_SDA: C33.1 R44.2 R46.2 U6.5 | length 347.8
  Top Layer w10: C33.1@2610,694.8 R44.2@2690,694.8 ; R46.2@2675,577.8 2675,614.65 2675,622.8 2678.08,619.72 R46.2@2700,597.8 ; R46.2@2685,580 R46.2@2690,580 ; R46.2@2690,621.65 R44.2@2690,694.8 ; R44.2@2690,697.24 R44.2@2690,694.8 ; R46.2@2693.74,588.74 U6.5@2800.63,588.74
ICP/SWD_SCL: J16.2 J17.2 R12.2 U2.31 | length 3098
  Top Layer w9: R12.2@3415.63,1163.74 3475.63,1163.74 3494.63,1182.74 3559.59,1182.74 3617.59,1124.74 3769.59,1124.74 3831.88,1062.45 ; 3831.9,1062.47 U2.31@3871.09,1062.47
  Top Layer w10: 3280.63,2228.74 3280.63,2078.74 ; J16.2@3350.63,2483.74 J16.2@3350.63,2458.74 3350.63,2308.74 3280.63,2238.74 3280.63,2078.74 ; R12.2@3413.63,1153.74 3408.63,1148.74 3373.63,1113.74 3290.63,1113.74 3259.38,1144.99 3259.38,1637.49 3280.63,1658.74 3280.63,2078.74
  Bottom Layer w12: J16.2@3350.63,2458.74 3440.63,2548.74 4060.63,2548.74 J17.2@4150.63,2458.74
ICP/SWD_SDA: J16.4 J17.4 R13.2 U2.33 | length 2398.9
  Top Layer w9: R13.2@3410.63,1213.74 3552.63,1213.74 3624.63,1141.74 3776.63,1141.74 3816.53,1101.84 U2.33@3871.09,1101.84
  Top Layer w10: R13.2@3413.63,1223.74 3410.63,1223.74 3407.13,1227.24 3370.63,1263.74 3300.63,1263.74 3283.38,1280.99 3283.38,1626.49 3305.63,1648.74 3305.63,2213.74 J16.4@3550.63,2458.74
  Bottom Layer w12: J16.4@3550.63,2458.74 3610.63,2518.74 3890.63,2518.74 J17.4@3950.63,2458.74
MG_PA0: CN1.114 U8.74 | length 761
  Top Layer w8: CN1.114@350.63,958.74 688.74,958.74 804.63,1074.63 804.63,1172.74 866.73,1234.84 U8.74@939.8,1234.84
MG_PA1: CN1.115 U8.75 | length 898.8
  Top Layer w8: CN1.115@250.63,858.74 300.63,908.74 668.74,908.74 823.63,1063.63 823.63,1166.74 875.98,1219.09 U8.75@939.8,1219.1
MG_PA2: CN1.116 U8.76 | length 795.2
  Top Layer w8: CN1.116@350.63,858.74 648.74,858.74 842.63,1052.63 842.63,1160.74 885.24,1203.35 U8.76@939.8,1203.35
MG_PA3: CN1.117 U8.77 | length 933.1
  Top Layer w8: CN1.117@250.63,758.74 300.63,808.74 628.74,808.74 861.63,1041.63 861.63,1154.74 894.49,1187.6 U8.77@939.8,1187.6
MG_PA4: CN1.118 U8.78 | length 829.5
  Top Layer w8: CN1.118@350.63,758.74 608.74,758.74 880.63,1030.63 880.63,1148.74 903.74,1171.85 U8.78@939.8,1171.85
MG_PA5: CN1.119 U8.79 | length 968.9
  Top Layer w8: CN1.119@250.63,658.74 300.63,708.74 588.74,708.74 899.63,1019.63 899.63,1145.45 910.28,1156.1 U8.79@939.8,1156.1
MG_PA6: CN1.120 U8.80 | length 865.8
  Top Layer w8: CN1.120@350.63,658.74 568.74,658.74 918.63,1008.63 918.63,1140.35 U8.80@939.8,1140.35
MG_PA7: CN1.2 U8.1 | length 792.1
  Top Layer w8: CN1.2@550.63,458.74 550.63,465.63 1026.42,941.42 U8.1@1026.42,1053.74
MG_PA8: CN1.3 U8.2 | length 898.6
  Top Layer w8: CN1.3@650.63,358.74 600.63,408.74 600.63,485.63 1042.17,927.17 U8.2@1042.17,1053.74
MG_PA9: CN1.4 U8.3 | length 763.7
  Top Layer w8: CN1.4@650.63,458.74 650.63,505.63 1057.91,912.91 U8.3@1057.91,1053.74
MG_PA10: CN1.5 U8.4 | length 870.2
  Top Layer w8: CN1.5@750.63,358.74 700.63,408.74 700.63,525.63 1073.66,898.66 U8.4@1073.66,1053.74
MG_PA11: CN1.6 U8.5 | length 735.3
  Top Layer w8: CN1.6@750.63,458.74 750.63,545.63 1089.41,884.41 U8.5@1089.41,1053.74
MG_PA12: CN1.7 U8.6 | length 841.9
  Top Layer w8: CN1.7@850.63,358.74 800.63,408.74 800.63,565.63 1105.16,870.16 U8.6@1105.16,1053.74
MG_PA13: CN1.8 U8.7 | length 707
  Top Layer w8: CN1.8@850.63,458.74 850.63,587 1120.91,857.28 U8.7@1120.91,1053.74
MG_PA14: CN1.9 U8.8 | length 813.5
  Top Layer w8: CN1.9@950.63,358.74 900.63,408.74 900.63,605.63 1136.65,841.65 U8.8@1136.65,1053.74
MG_PA15: CN1.10 U8.9 | length 678.6
  Top Layer w8: CN1.10@950.63,458.74 950.63,625.63 1152.4,827.4 U8.9@1152.4,1053.74
MG_PB0: CN1.11 R48.1 U8.10 | length 1987.8
  Top Layer w8: 1000.63,645.63 1168.15,813.15 U8.10@1168.15,1053.74
  Top Layer w10: 1000.63,645.63 1000.63,408.74 CN1.11@1050.63,358.74
  Bottom Layer w12: CN1.11@1050.63,358.74 1050.63,334.37 1205,180 2140,180 R48.1@2165,180
MG_PB1: CN1.12 R52.1 U8.11 | length 2049.2
  Top Layer w8: CN1.12@1050.63,458.74 1050.63,665.63 1183.9,798.9 U8.11@1183.9,1053.74
  Bottom Layer w12: CN1.12@1050.63,458.74 1000.63,408.74 1000.63,333.74 1184.37,150 2100,150 2141.1,108.9 R52.1@2155,95
MG_PB2: CN1.13 R49.2 U8.12 | length 2497.3
  Top Layer w8: CN1.13@1150.63,358.74 1100.63,408.74 1100.63,685.63 1199.65,784.65 U8.12@1199.65,1053.74
  Bottom Layer w12: CN1.13@1150.63,358.74 1150.63,284.37 1225,210 1992.43,210 2080.22,297.8 2480,297.8 2550,227.8 2650,227.8 2695,272.8 R49.2@2700,277.8
MG_PB3: CN1.14 R50.2 U8.13 | length 2390.7
  Top Layer w8: CN1.14@1150.63,458.74 1150.63,705.63 1215.39,770.39 U8.13@1215.39,1053.74
  Bottom Layer w12: CN1.14@1150.63,458.74 1200.63,408.74 1200.63,284.37 1243.71,241.29 1981.29,241.29 2067.8,327.8 2650,327.8 2695,372.8 R50.2@2700,377.8
MG_PB4: CN1.27 U8.18 | length 1118.4
  Top Layer w8: U8.18@1294.13,1053.74 1294.13,730.87 1452.62,572.38 1781.99,572.38 1800.63,553.74 1800.63,408.74 CN1.27@1850.63,358.74
MG_PB5: CN1.28 U8.19 | length 1020.7
  Top Layer w8: U8.19@1309.88,1053.74 1309.88,745.12 1461.41,593.59 1805.78,593.59 1850.63,548.74 CN1.28@1850.63,458.74
MG_PB6: CN1.29 U8.20 | length 1161.5
  Top Layer w8: U8.20@1325.63,1053.74 1325.63,759.37 1470.19,614.81 1824.56,614.81 1900.63,538.74 1900.63,429.37 1950.63,379.37 CN1.29@1950.63,358.74
MG_PB7: CN1.32 U8.21 | length 1162
  Top Layer w8: U8.21@1412.24,1140.35 1429.02,1140.35 1435.63,1133.74 1435.63,751.09 1512.98,673.74 2135.63,673.74 CN1.32@2150.63,658.74
MG_PB8(TX): CN1.33 J5.2 J15.2 U2.13 U8.22 | length 3005
  Top Layer w8: U8.22@1412.24,1156.1 1441.45,1156.1 1455.63,1141.93 1455.63,759.37 1521.26,693.74 2100.63,693.74 2115.63,708.74 2200.63,708.74 CN1.33@2250.63,758.74 2290.63,758.74 2310.63,778.74 v4(2480.63,778.74)
  Top Layer w10: J15.2@2950.63,1058.74 J5.2@3150.63,1058.74 3210.63,998.74 3210.63,883.74 3233.63,860.74 3525.63,860.74 ; 3485.63,860.74 3525.63,860.74 ; U2.13@3594.08,884.39 3594.08,860.74 3525.63,860.74
  Bottom Layer w12: v4(2480.63,778.74) 2475.63,783.74 2475.63,840.63 2618.74,983.74 2875.63,983.74 J15.2@2950.63,1058.74
MG_PB9(RX): CN1.34 J5.1 J15.1 U2.14 U8.23 | length 2924.3
  Top Layer w8: U8.23@1412.24,1171.85 1452.98,1171.85 1475.63,1149.2 1475.63,769.37 1531.26,713.74 2080.63,713.74 2125.63,758.74 CN1.34@2150.63,758.74 2165.63,758.74 2215.63,808.74 2280.63,808.74 2300.63,828.74 v4(2510.63,828.74)
  Top Layer w10: J15.1@2950.63,958.74 J5.1@3150.63,958.74 3156.4,952.97 3156.4,887.97 3205.63,838.74 3570.63,838.74 ; 3485.63,838.74 3570.63,838.74 ; U2.14@3613.77,884.39 3613.77,846.88 3605.63,838.74 3570.63,838.74
  Bottom Layer w12: v4(2510.63,828.74) 2637.35,955.46 J15.1@2947.35,955.46
MG_PB10: CN1.35 R47.1 SW3.1 U8.24 | length 1973
  Top Layer w8: U8.24@1412.24,1187.6 1461.77,1187.6 1495.63,1153.74 1495.63,838.15 SW3.1@1555.04,778.74 ; SW3.1@1565.04,788.74 1620.04,733.74 2045.63,733.74 2120.63,808.74 2185.63,808.74 2235.63,858.74 CN1.35@2250.63,858.74 2530.63,858.74 2540,849.37 2540,539.78 2561.04,518.74 ; 2541.78,538 2561.04,518.74 ; R47.1@2617,518.74 2607,518.74 2561.04,518.74
MG_PB11: CN1.36 R46.1 SW4.1 U8.25 | length 1804
  Top Layer w8: U8.25@1412.24,1203.35 1471.02,1203.35 1515.63,1158.74 1515.63,1063.74 SW4.1@1566.73,1012.64 ; SW4.1@1562.83,1008.74 1563.94,1009.84 1609.09,1055 2044.37,1055 2090.63,1008.74 2090.63,918.74 CN1.36@2150.63,858.74 2200.63,908.74 2285.63,908.74 2310.63,883.74 2545.63,883.74 2565,864.37 R46.1@2565,580 ; 2565.06,609.31 2580.63,593.74 R46.1@2580.63,597.8 ; R46.1@2600,587.8 R46.1@2600,597.8
MG_PB12: CN1.37 U8.26 | length 992.7
  Top Layer w8: U8.26@1412.24,1219.1 1480.28,1219.09 1535.63,1163.74 1535.63,1084.37 1545,1075 2059.37,1075 2125.63,1008.74 2200.63,1008.74 CN1.37@2250.63,958.74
